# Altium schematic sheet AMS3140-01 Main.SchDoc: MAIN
size A4; Author: psalek; DrawnBy: PS; Engineer: Przemysław Kownacki; Organization: VIGO System S.A.; Address1: ul. Poznańska 129/133; Address2: 05-580 Ozarów Mazowiecki; Address3: POLAND; DocumentNumber: aaaa; Revision: 01; SheetNumber: 1; SheetTotal: 7
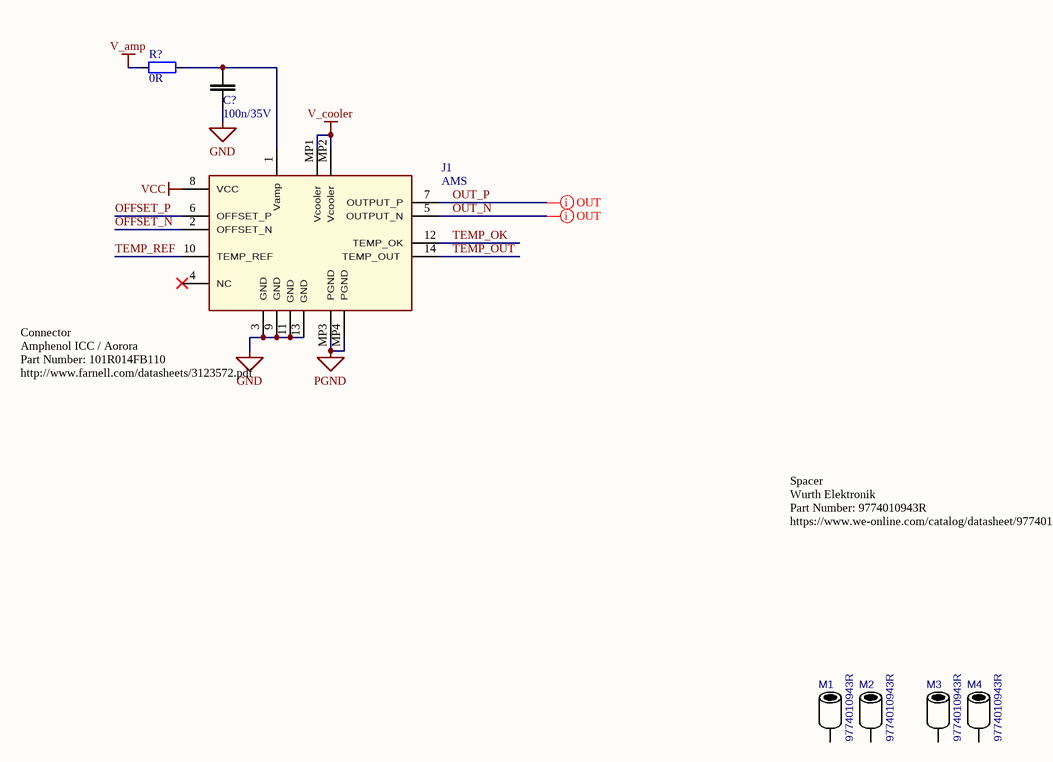
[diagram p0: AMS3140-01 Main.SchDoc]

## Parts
C?  100n/35V  [0402_CAP]
J1  AMS  [101R014FB110]
M1  9774010943R  [TP_THT_1500_3000]
M2  9774010943R  [TP_THT_1500_3000]
M3  9774010943R  [TP_THT_1500_3000]
M4  9774010943R  [TP_THT_1500_3000]
R?  0R  [0402_RES]

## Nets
GND: C?.1 J1.3(GND) J1.9(GND) J1.11(GND) J1.13(GND)
PGND: J1.MP3(PGND) J1.MP4(PGND)
V_amp: R?.2
V_cooler: J1.MP1(Vcooler) J1.MP2(Vcooler)
VCC: J1.8(VCC)
OFFSET_N: J1.2(OFFSET_N)
OFFSET_P: J1.6(OFFSET_P)
OUT_N: J1.5(OUTPUT_N)
OUT_P: J1.7(OUTPUT_P)
TEMP_OK: J1.12(TEMP_OK)
TEMP_OUT: J1.14(TEMP_OUT)
TEMP_REF: J1.10(TEMP_REF)
NetC?_2: C?.2 J1.1(Vamp) R?.1

Not connected (* = marked no-connect by the designer): J1 4(NC)*; M1 1; M2 1; M3 1; M4 1

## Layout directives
differential pair; rule Matched Net Lengths [Tolerance = 2mm]: OUT_N, OUT_P

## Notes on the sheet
- (near J1) Connector
  Amphenol ICC / Aorora
  Part Number: 101R014FB110
  http://www.farnell.com/datasheets/3123572.pdf
- Spacer
  Wurth Elektronik
  Part Number: 9774010943R
  https://www.we-online.com/catalog/datasheet/9774010943.pdf

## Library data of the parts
C? = cap_0402_100n_35V: Ceramic capacitor; Manufacturer: Taiyo Yuden; SMDorTHT: SMD
J1 = mod_AMS3140: Manufacturer: Vigo System; SMDorTHT: SMD
M1-M4 = m_spacer_1mm_fi2.25_WA-SMST_9774010943: Manufacturer: Wurth Elektronik; SMDorTHT: SMD
R? = res_0402_0R: Resistior; SMDorTHT: SMD; pp_waste: 30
